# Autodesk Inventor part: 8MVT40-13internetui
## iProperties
Created: 2009-10
Part Number: 8MVT40-13internetui
Document SubType Name: Modeling
Designer: Darius
Author: Darius
Translation Standard: STEP AP203
File Name: 8MVT40-13.STEP
Preprocessor: SolidWorks 2003240
Postprocessor: Build: 272, Release: 10 SP3a - Date: Thu 12/15/2005
Sent Units: MILLIMETERS
Uncertainty: 1e-05
